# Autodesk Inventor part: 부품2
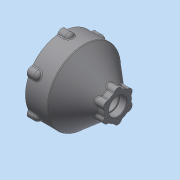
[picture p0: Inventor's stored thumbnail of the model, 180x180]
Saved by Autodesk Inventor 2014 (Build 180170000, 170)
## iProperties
Created: 2026-05
Part Number: 부품2
Material: 일반
Document SubType Name: Modeling
Designer: dg
Density: 1 g/cm^3
Appearance: 기본값
Author: dg
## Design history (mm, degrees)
sketch "스케치1"
  geometry: L1 (0, 0)-(-63, 0); L2 (-63, 0)-(-63, 82); L3 (-63, 82)-(-13, 82); L4 (-13, 82)-(48.375, 30.5); L5 (48.375, 30.5)-(63, 30.5); L6 (63, 30.5)-(63, 0); L7 (63, 0)-(0, 0); L8 (-63, 0)-(63, 0)
  constraints: 16 end point, 3 parallel, 2 collinear, 1 horizontal, 1 perpendicular
  dimensions: "d0" = 61 diameter of L5 L7; "d1" = 164 diameter of L3 L1; "d2" = 40 deg angle of L3 L4; "d3" = 50 distance of L2.end L3.end; "d4" = 126 distance between parallel lines of L2 L6; "d5" = 63 distance from line of L2 L1.start
revolve "회전1" sketch "스케치1" stored, may be unused: angle "d6" = 90 deg
sketch "스케치6" dims "d73" = 54
  geometry: L1 (0, 0)-(0, 86.548); L2 (0, 0)-(28.257, 48.942); C1 r 30.5 at (0, 0) reference; C2 r 9 at (13.5, 23.383)
  constraints: 4 end point, 1 centre point, 1 coincident, 1 point on line, 1 vertical, 3 other
  dimensions: "d74" = 30 deg angle of L1 L2; "d75" = 18 diameter of C2
extrude "돌출2" join sketch "스케치6" stored distance "d76" = 20; taper "d77" = 0 deg
sketch "스케치11" dims "d109" = 158
  geometry: L1 (0, 0)-(0, 114.814); L2 (0, 0)-(60.185, 104.244); C1 r 82 at (0, 0) reference; C2 r 10 at (39.5, 68.416)
  constraints: 4 end point, 1 centre point, 1 coincident, 1 point on line, 1 vertical, 3 other
  dimensions: "d110" = 30 deg angle of L1 L2; "d111" = 20 diameter of C2
extrude "돌출4" join sketch "스케치11" distance "d112" = 25; taper "d113" = 0 deg
fillet "모깎기13" dims "d129" = 10
fillet "모깎기14" dims "d130" = 3
sketch "스케치3"
  geometry: L1 (0, 0)-(-63, 0); L2 (0, 0)-(63, 0); L3 (63, 0)-(47, 0); L4 (47, 0)-(47, 20); L5 (47, 20)-(63, 20); L6 (63, 20)-(63, 0); L7 (47, 0)-(31, 0); L8 (31, 0)-(31, 17.5); L9 (31, 17.5)-(47, 17.5); L10 (47, 17.5)-(47, 0); L11 (31, 0)-(19, 0); L12 (19, 0)-(19, 20); L13 (19, 20)-(31, 20); L14 (31, 20)-(31, 0); L15 (19, 0)-(15, 0); L16 (15, 0)-(15, 37); L17 (15, 37)-(19, 37); L18 (19, 37)-(19, 0); L19 (15, 0)-(-1, 0); L20 (-1, 0)-(-1, 40); L21 (-1, 40)-(15, 40); L22 (15, 40)-(15, 0); L23 (-1, 0)-(-21, 0); L24 (-21, 0)-(-21, 56); L25 (-21, 56)-(-1, 56); L26 (-1, 56)-(-1, 0); L27 (-21, 0)-(-26, 0); L28 (-26, 0)-(-26, 68); L29 (-26, 68)-(-21, 68); L30 (-21, 68)-(-21, 0); L31 (-26, 0)-(-63, 0); L32 (-63, 0)-(-63, 73); L33 (-63, 73)-(-26, 73); L34 (-26, 73)-(-26, 0)
  constraints: 68 end point, 17 equal length, 9 horizontal, 8 perpendicular
  dimensions: "d14" = 63 distance of L1.start L1.end; "d15" = 63 distance of L1.start L2.end; "d16" = 146 diameter of L33 L2; "d17" = 136 diameter of L29 L2; "d18" = 37 distance between parallel lines of L32 L34; "d19" = 5 distance between parallel lines of L28 L30; "d20" = 25 distance between parallel lines of L20 L28; "d21" = 112 diameter of L25 L2; "d22" = 80 diameter of L21 L2; "d23" = 16 distance between parallel lines of L6 L4; "d24" = 40 diameter of L5 L2; "d25" = 35 diameter of L9 L2; "d26" = 12 distance between parallel lines of L12 L8; "d27" = 40 diameter of L13 L2; "d28" = 16 distance between parallel lines of L26 L22; "d29" = 20 distance between parallel lines of L18 L20; "d30" = 74 diameter of L17 L2
revolve "회전2" sketch "스케치3" stored, may be unused: angle "d31" = 90 deg
chamfer "모따기1" distance "d32" = 1; stored, may be unused: second distance "d33" = 2, angle "d34" = 45 deg
fillet "모깎기1" dims "d35" = 3
chamfer "모따기2" distance "d36" = 1; stored, may be unused: second distance "d37" = 2, angle "d38" = 45 deg
fillet "모깎기2" dims "d39" = 3
chamfer "모따기3" distance "d40" = 1; stored, may be unused: second distance "d41" = 2, angle "d42" = 45 deg
fillet "모깎기3" dims "d43" = 1
chamfer "모따기4" distance "d44" = 1; stored, may be unused: second distance "d45" = 2, angle "d46" = 45 deg
fillet "모깎기4" dims "d47" = 3
chamfer "모따기5" distance "d48" = 1; stored, may be unused: second distance "d49" = 2, angle "d50" = 45 deg
fillet "모깎기5" dims "d51" = 0.6
fillet "모깎기6" dims "d52" = 3
fillet "모깎기7" dims "d53" = 3
sketch "스케치5" dims "d61" = 124
  geometry: L1 (0, 0)-(0, 104.094); L2 (0, 0)-(53.078, 91.934); C1 r 68 at (0, 0) reference; 1 further point
  constraints: 4 end point, 1 coincident, 1 point on line, 1 vertical, 3 other
  dimensions: "d62" = 30 deg angle of L1 L2
hole "구멍2" sketch "스케치5" at (31, 53.694) diameter "d63" = 3.242; stored, may be unused: countersink angle "d67" = 90 deg, drill point angle "d69" = 118 deg; dims "d64" = 8, "d65" = 4, "d66" = 2, "d68" = 10
sketch "스케치7"
  geometry: A1 r 9 centre (40.5, 23.383) between (49.165, 20.951) and (34.062, 29.671) reference; A2 r 9 centre (13.5, 23.383) between (19.938, 29.671) and (4.835, 20.951) reference; A3 r 9 centre (0, 0) between (-2.227, 8.72) and (-2.227, -8.72) reference; A4 r 9 centre (13.5, -23.383) between (4.835, -20.951) and (19.938, -29.671) reference; A5 r 9 centre (40.5, -23.383) between (34.062, -29.671) and (49.165, -20.951) reference; A6 r 9 centre (54, 0) between (56.227, -8.72) and (56.227, 8.72) reference; 6 further points
  constraints: 6 coincident
hole "구멍3" sketch "스케치7" at (13.5, 23.383), (0, 0), (40.5, 23.383), (54, 0), (40.5, -23.383), (13.5, -23.383) diameter "d81" = 3.242; stored, may be unused: countersink angle "d85" = 90 deg, drill point angle "d87" = 118 deg; dims "d82" = 8, "d83" = 4, "d84" = 2, "d86" = 10
fillet "모깎기8" dims "d88" = 3
sketch "스케치14"
  geometry: A1 r 10 centre (0, 0) between (-3.968, 9.179) and (-3.968, -9.179) reference; A2 r 10 centre (39.5, -68.416) between (29.567, -67.263) and (45.465, -76.442) reference; A3 r 10 centre (118.5, -68.416) between (112.535, -76.442) and (128.433, -67.263) reference; A4 r 10 centre (158, 0) between (161.968, -9.179) and (161.968, 9.179) reference; A5 r 10 centre (118.5, 68.416) between (128.433, 67.263) and (112.535, 76.442) reference; A6 r 10 centre (39.5, 68.416) between (45.465, 76.442) and (29.567, 67.263) reference; 6 further points
  constraints: 6 coincident
hole "구멍6" sketch "스케치14" at (39.5, 68.416), (0, 0), (118.5, 68.416), (158, 0), (118.5, -68.416), (39.5, -68.416) diameter "d134" = 4.917; stored, may be unused: countersink angle "d138" = 90 deg, drill point angle "d140" = 118 deg; dims "d135" = 12, "d136" = 4, "d137" = 2, "d139" = 14
node "작업 평면3"
sketch "스케치15"
  geometry: L1 (25, 30.625)-(25, -30.625) reference; 2 further points
  constraints: 1 horizontal alignment, 1 other
  dimensions: "d141" = 20 distance from line of L1 point (5, 0)
feature "엠보싱3" sketch "스케치15" dims "d14" = 63, "d15" = 63, "d16" = 146, "d17" = 136, "d18" = 37, "d19" = 5, "d20" = 25, "d21" = 112, "d22" = 80, "d23" = 16, "d24" = 40, "d25" = 35, "d26" = 12, "d27" = 40, "d28" = 16, "d29" = 20, "d30" = 74, "d142" = 0.5, "d143" = 0
node "솔리드1"
pattern_circular "원형 패턴6" dims "d132" = 360 deg
pattern_circular "원형 패턴2" dims angle "d71" = 360 deg
pattern_circular "원형 패턴3" dims angle "d79" = 360 deg
